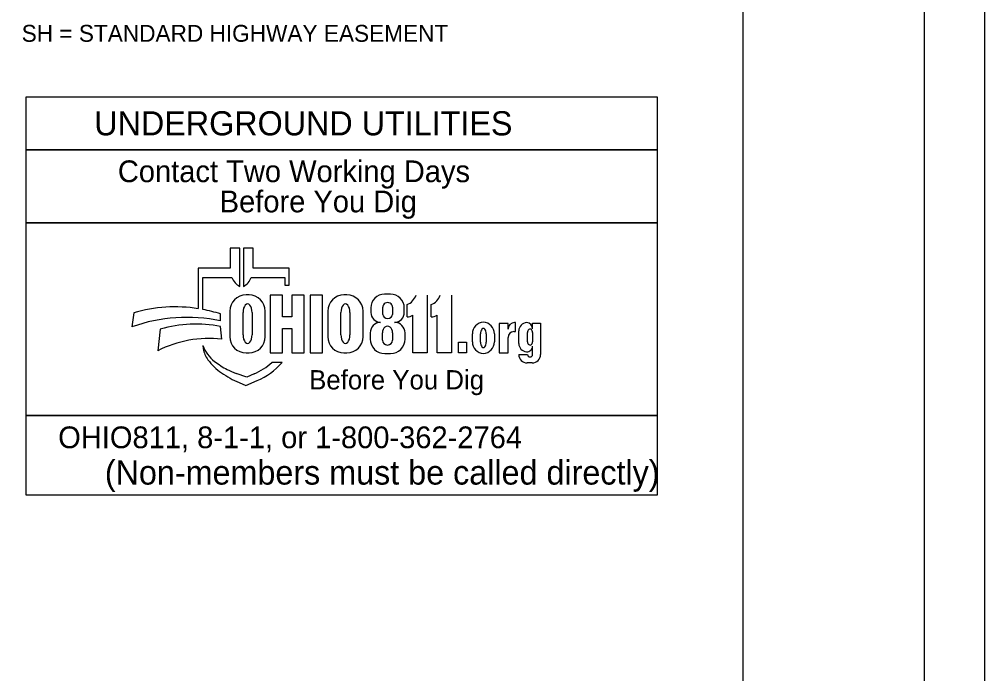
# Model space of a CAD drawing. Extents: x 0 to 104, y 0 to 37.
# Drawn here: x 26.01 to 34, y 5.42 to 10.84 of the extents above; entities that cross this region are included whole.
import ezdxf

# ---------------------------------------------------------------- set-up
doc = ezdxf.new("R2010")
doc.units = 0
for name, color, linetype in [('SC_Scratch3', 7, 'Continuous'), ('SH_Cut_Line', 7, 'Continuous'), ('SH_Data', 7, 'Continuous'), ('SH_Named_Boundary', 7, 'Continuous')]:
    doc.layers.add(name, color=color, linetype=linetype)

# ---------------------------------------------------------------- blocks, each defined once
blk = doc.blocks.new('OUPS Logo')
at = {"layer": 'SH_Cut_Line'}
for p, q in [((-0.9684, 0.4019), (-1.0485, 0.4019)), ((-1.0485, 0.4019), (-1.0485, 0.2354)), ((-0.9684, 0.0851), (-0.9684, 0.4019)), ((-0.8572, 0.4019), (-0.9373, 0.4019)), ((-0.9373, 0.4019), (-0.9373, 0.0851)), ((-0.8572, 0.2354), (-0.8572, 0.4019)), ((-1.0485, 0.2354), (-1.3114, 0.2354)), ((-1.3114, 0.2354), (-1.3114, -0.0991)), ((-0.5595, 0.2354), (-0.8572, 0.2354)), ((-0.5595, 0.0952), (-0.5595, 0.2354)), ((-1.2736, -0.1057), (-1.2736, 0.1585)), ((-1.2736, 0.1585), (-1.033, 0.1585)), ((-0.8727, 0.1585), (-0.5943, 0.1585)), ((-0.5943, 0.1585), (-0.5943, 0.0952)), ((-0.5943, 0.0952), (-0.5595, 0.0952)), ((-0.8917, 0.0141), (-0.9164, 0.0141)), ((-0.6138, 0.0127), (-0.7153, 0.0127)), ((-0.7153, 0.0127), (-0.7153, -0.4653)), ((-0.0809, 0.0141), (-0.1056, 0.0141)), ((0.2802, 0.0207), (0.2313, 0.0207)), ((0.5839, 0.0127), (0.5839, -0.4653)), ((0.784, 0.0127), (0.784, -0.4653)), ((0.4172, -0.1676), (0.4172, -0.0658)), ((0.6173, -0.1676), (0.6173, -0.0658)), ((-1.8465, -0.1333), (-1.8605, -0.25)), ((-1.1275, -0.201), (-1.1275, -0.143)), ((-1.05, -0.1195), (-1.05, -0.3317)), ((-0.9411, -0.3146), (-0.9411, -0.1319)), ((-0.8667, -0.1319), (-0.8667, -0.3146)), ((-0.758, -0.3317), (-0.758, -0.1195)), ((-0.2393, -0.1195), (-0.2393, -0.3317)), ((-0.1304, -0.3146), (-0.1304, -0.1319)), ((-0.056, -0.1319), (-0.056, -0.3146)), ((0.0527, -0.3317), (0.0527, -0.1195)), ((0.1173, -0.0933), (0.1173, -0.1296)), ((0.2161, -0.1466), (0.2161, -0.0879)), ((0.297, -0.0879), (0.297, -0.1466)), ((0.3942, -0.1296), (0.3942, -0.0933)), ((0.4655, -0.4653), (0.4655, -0.1537)), ((0.6656, -0.4653), (0.6656, -0.1537)), ((1.2528, -0.2219), (1.1798, -0.2219)), ((1.1798, -0.2219), (1.1798, -0.4653)), ((1.2528, -0.269), (1.2528, -0.2219)), ((1.3135, -0.2142), (1.3076, -0.2142)), ((1.3135, -0.2887), (1.3135, -0.2142)), ((1.4567, -0.2668), (1.4567, -0.2205)), ((1.4567, -0.2205), (1.5217, -0.2205)), ((1.5217, -0.2205), (1.5217, -0.4788)), ((-1.6258, -0.2685), (-1.6478, -0.448)), ((-1.1174, -0.3515), (-1.1267, -0.2455)), ((-0.6138, -0.4653), (-0.6138, -0.2632)), ((0.1118, -0.2997), (0.1118, -0.3506)), ((0.2126, -0.3595), (0.2126, -0.2984)), ((0.2975, -0.2984), (0.2975, -0.3595)), ((0.4002, -0.3506), (0.4002, -0.2997)), ((0.9578, -0.3744), (0.9578, -0.3067)), ((1.025, -0.3756), (1.025, -0.3067)), ((1.0731, -0.3067), (1.0731, -0.3756)), ((1.1403, -0.3067), (1.1403, -0.3744)), ((1.302, -0.2887), (1.3135, -0.2887)), ((1.3418, -0.387), (1.3418, -0.283)), ((1.414, -0.3731), (1.414, -0.2969)), ((1.4567, -0.2969), (1.4567, -0.3731)), ((1.2528, -0.4653), (1.2528, -0.3379)), ((-1.2746, -0.4052), (-1.2701, -0.432)), ((-0.9164, -0.4653), (-0.8917, -0.4653)), ((-0.7153, -0.4653), (-0.6138, -0.4653)), ((-0.1056, -0.4653), (-0.0809, -0.4653)), ((0.2327, -0.4715), (0.2793, -0.4715)), ((0.5839, -0.4653), (0.4655, -0.4653)), ((0.784, -0.4653), (0.6656, -0.4653)), ((1.1798, -0.4653), (1.2528, -0.4653)), ((1.3418, -0.4788), (1.414, -0.4788)), ((1.4567, -0.4788), (1.4567, -0.4095)), ((-0.6162, -0.5453), (-0.702, -0.5453)), ((-0.6186, -0.548), (-0.6162, -0.5453)), ((1.4519, -0.5486), (1.4116, -0.5486)), ((-0.9096, -0.6661), (-0.9984, -0.6355)), ((-0.9744, -0.7118), (-0.9186, -0.7363)), ((-0.9186, -0.7363), (-0.8241, -0.6953)), ((-0.8483, -0.6395), (-0.9096, -0.6661)), ((2.4876, -1.6436), (-2.7373, -1.6436))]:
    blk.add_line(p, q, dxfattribs=at)
for points in [[(-2.7373, 1.6564), (2.4876, 1.6564), (2.4876, 1.2164), (-2.7373, 1.2164)], [(-2.7373, 1.2164), (2.4876, 1.2164), (2.4876, 0.6114), (-2.7373, 0.6114)], [(-2.7373, 0.6114), (2.4876, 0.6114), (2.4876, -0.9836), (-2.7373, -0.9836)], [(0.842, -0.3756), (0.9079, -0.3756), (0.9079, -0.4653), (0.842, -0.4653)], [(-2.7373, -0.9836), (2.4876, -0.9836), (2.4876, -1.6436), (-2.7373, -1.6436)]]:
    blk.add_lwpolyline(points, close=True, dxfattribs=at)
for points in [[(-0.6138, -0.2632), (-0.5377, -0.2632), (-0.5377, -0.4653), (-0.4361, -0.4653), (-0.4361, 0.0127), (-0.5377, 0.0127), (-0.5377, -0.1676), (-0.6138, -0.1676), (-0.6138, 0.0127)], [(-0.3854, -0.4653), (-0.2826, -0.4653), (-0.2826, 0.0127), (-0.3854, 0.0127), (-0.3854, -0.4653)], [(0.1982, -0.2132), (0.1982, -0.2133)], [(0.3138, -0.2133), (0.3137, -0.2132)]]:
    blk.add_lwpolyline(points, dxfattribs=at)
for centre, radius, start, end in [((-0.8965, 0.2134), 0.1471, 201.92963, 240.74693), ((-1.0092, 0.2134), 0.1471, 299.25307, 338.07037), ((-0.9164, -0.1195), 0.1337, 90, 180), ((-0.8917, -0.1195), 0.1337, 0, 90), ((-0.1056, -0.1195), 0.1337, 90, 180), ((-0.0809, -0.1195), 0.1337, 0, 90), ((0.2313, -0.0933), 0.114, 90, 180), ((0.2802, -0.0933), 0.114, 0, 90), ((0.3665, 0.0563), 0.1322, 292.55722, 340.73552), ((0.5666, 0.0563), 0.1322, 292.55722, 340.73552), ((-1.5028, -1.3076), 1.2235, 81.00071, 106.31438), ((-1.5028, -1.3076), 1.2235, 72.14025, 79.20744), ((0.2009, -0.1296), 0.0837, 180, 268.14422), ((0.3105, -0.1296), 0.0837, 272.20579, 0), ((0.4053, -0.036), 0.1322, 275.17327, 297.09312), ((0.6054, -0.036), 0.1322, 275.17327, 297.09312), ((-1.4085, -1.5034), 1.3324, 77.82382, 109.82736), ((-1.3272, -1.3207), 1.0937, 79.44002, 105.84672), ((0.1982, -0.2997), 0.0865, 90, 180), ((0.3138, -0.2997), 0.0865, 0, 90), ((1.0534, -0.3067), 0.0956, 92.58863, 180), ((1.0447, -0.3067), 0.0956, 0, 87.41137), ((1.3076, -0.269), 0.0548, 90, 180), ((1.4103, -0.283), 0.0686, 92.68649, 180), ((1.4043, -0.2668), 0.0524, 0, 86.92624), ((1.302, -0.3379), 0.0493, 90, 180), ((-1.2196, -1.2956), 0.9496, 83.82483, 116.80206), ((-0.9164, -0.3317), 0.1337, 180, 270), ((-0.8917, -0.3317), 0.1337, 270, 0), ((-0.1056, -0.3317), 0.1337, 180, 270), ((-0.0809, -0.3317), 0.1337, 270, 0), ((0.2327, -0.3506), 0.1209, 180, 270), ((0.2793, -0.3506), 0.1209, 270, 0), ((1.0534, -0.3744), 0.0956, 180, 267.41137), ((1.0447, -0.3744), 0.0956, 272.58863, 0), ((1.4109, -0.387), 0.0692, 180, 265.71324), ((-0.9947, -0.2975), 0.2999, 201.04565, 232.53137), ((-1.059, -0.3959), 0.2141, 189.68174, 216.08842), ((1.4116, -0.4788), 0.0699, 180, 270), ((1.41, -0.4095), 0.0467, 264.78254, 0), ((1.4519, -0.4788), 0.0699, 270, 0), ((-0.8593, -0.2504), 0.4612, 216.08842, 235.7167), ((-0.7071, 0.0778), 0.7728, 232.53137, 241.79401), ((-1.0625, -0.1458), 0.5381, 293.45821, 312.07118), ((-1.0625, -0.1458), 0.599, 293.45821, 317.82862), ((-0.6106, 0.1145), 0.9028, 235.7167, 246.23245), ((-0.8343, -0.1594), 0.5035, 241.79401, 250.98207)]:
    blk.add_arc(centre, radius, start, end, dxfattribs=at)
for centre, major_axis, ratio, start_param, end_param in [((-0.9039, -0.1319), (0, 0.0723), 0.514403, 4.712389, 7.853982), ((-0.0932, -0.1319), (0, 0.0723), 0.514403, 4.712389, 7.853982), ((0.2566, -0.0879), (0.0404, 0), 0.969373, 0, 3.141593), ((0.2566, -0.1466), (0.0404, 0), 0.818453, 3.141593, 6.283185), ((-0.9039, -0.3146), (0, 0.0723), 0.514403, 1.570796, 4.712389), ((-0.0932, -0.3146), (0, 0.0723), 0.514403, 1.570796, 4.712389), ((0.255, -0.2984), (0, 0.0535), 0.794529, 4.712389, 7.853982), ((1.0491, -0.3067), (0, 0.0434), 0.553236, 4.712389, 7.853982), ((1.4353, -0.2969), (0, 0.0275), 0.777179, 4.712389, 7.853982), ((0.255, -0.3595), (0.0425, 0), 0.959837, 3.141593, 6.283185), ((1.0491, -0.3756), (0, 0.046), 0.522014, 1.570796, 4.712389), ((1.4353, -0.3731), (0, 0.0275), 0.777179, 1.570796, 4.712389), ((1.4353, -0.4788), (0.0214, 0), 0.959012, 3.141593, 6.283185)]:
    blk.add_ellipse(centre, major_axis=major_axis, ratio=ratio, start_param=start_param, end_param=end_param, dxfattribs=at)
for s, height, p in [('UNDERGROUND UTILITIES', 0.2, (-2.1727, 1.3364)), ('Contact Two Working Days', 0.18, (-1.9775, 0.9489)), ('Before You Dig', 0.18, (-1.1343, 0.6989)), ('Before You Dig', 0.15972, (-0.3939, -0.7683)), ('OHIO811, 8-1-1, or 1-800-362-2764', 0.18, (-2.4715, -1.2549)), ('(Non-members must be called directly)', 0.2, (-2.0852, -1.5565))]:
    blk.add_text(s, height=height, dxfattribs=at).set_placement(p)

msp = doc.modelspace()

# ---------------------------------------------------------------- linework, layer by layer
at = {"layer": 'SC_Scratch3'}
msp.add_lwpolyline([(0, 0), (34, 0), (34, 22), (0, 22)], close=True, dxfattribs=at)
at = {"layer": 'SH_Named_Boundary'}
msp.add_line((32, 0.5), (32, 21.5), dxfattribs=at)
msp.add_lwpolyline([(1.5, 21.5), (33.5, 21.5), (33.5, 0.5), (1.5, 0.5)], close=True, dxfattribs=at)

# ---------------------------------------------------------------- block references
at = {"layer": 'SH_Data'}
msp.add_blockref('OUPS Logo', (28.8008, 8.5442), dxfattribs=at)

# ---------------------------------------------------------------- texts
msp.add_text('SH = STANDARD HIGHWAY EASEMENT', height=0.14, dxfattribs=at).set_placement((26.0271, 10.6559))

doc.saveas('drawing.dxf')
